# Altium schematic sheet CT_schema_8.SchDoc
size 370 x 245 mm
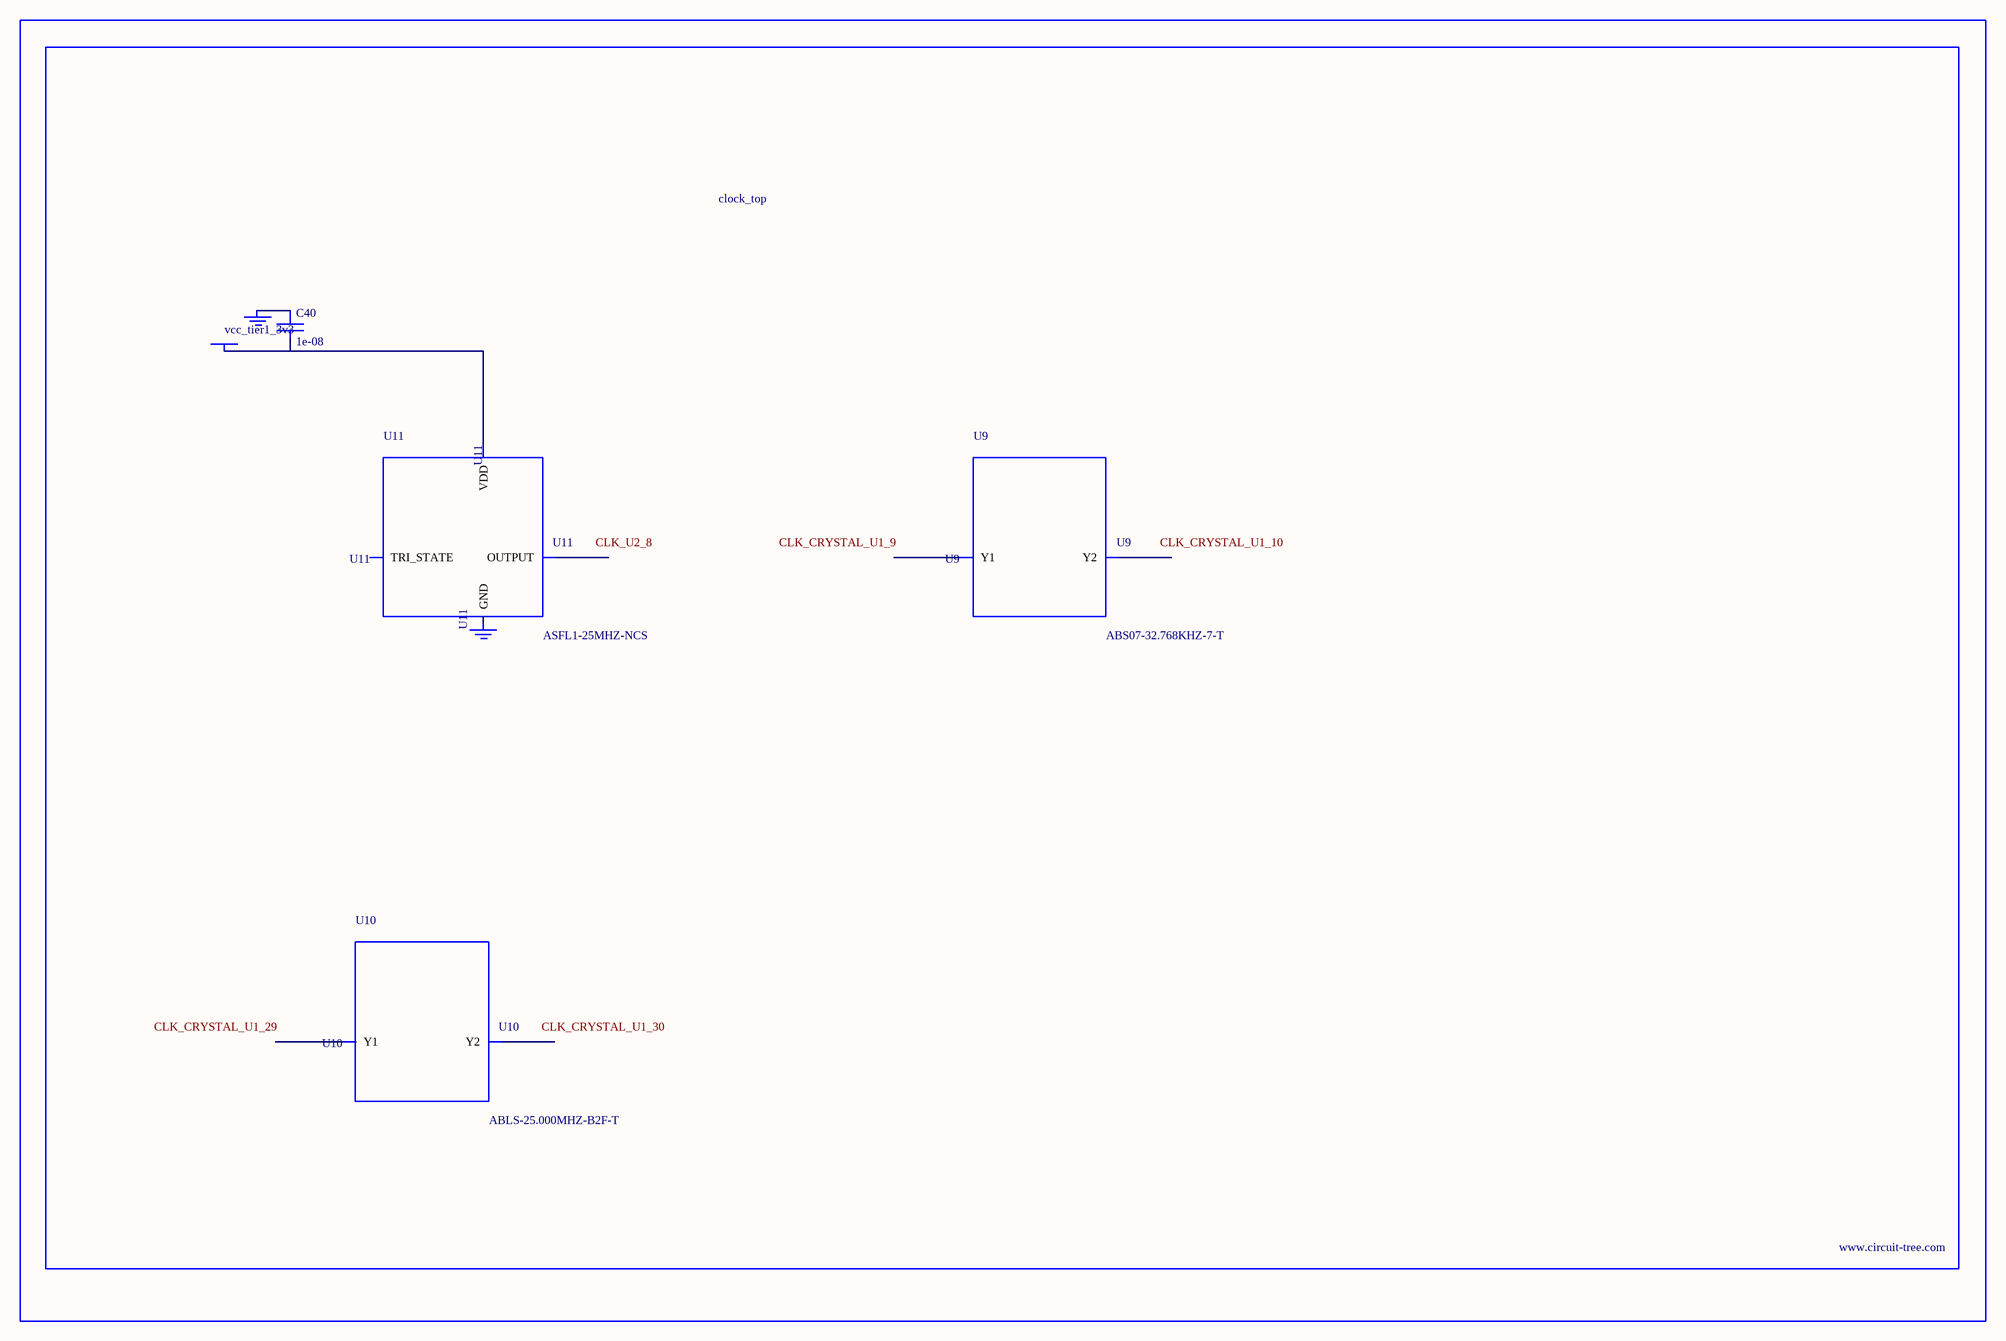
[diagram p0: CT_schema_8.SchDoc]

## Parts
BORDER7  (no value)
C40  1e-08  [C0402]
GND_INSTANCE_7_0  (no value)
GND_INSTANCE_7_1  (no value)
POWER_INSTANCE_7_0  vcc_tier1_3v3
U9  ABS07-32.768KHZ-7-T  [ABS07-32.768KHZ-7-T]
U10  ABLS-25.000MHZ-B2F-T  [ABLS-25.000MHZ-B2F-T]
U11  ASFL1-25MHZ-NCS  [ASFL1]

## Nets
NetC40_1: C40.1 GND_INSTANCE_7_0.0(GND)
NetC40_2: C40.2 POWER_INSTANCE_7_0.0(PWR) U11.4(VDD)

Not connected (* = marked no-connect by the designer): GND_INSTANCE_7_1 0(GND); U9 1(Y1) 2(Y2); U10 1(Y1) 2(Y2); U11 1(TRI_STATE) 2(GND) 3(OUTPUT)

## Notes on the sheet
- Labels drawn without touching a wire or pin: CLK_CRYSTAL_U1_9, CLK_CRYSTAL_U1_10, CLK_CRYSTAL_U1_29, CLK_CRYSTAL_U1_30, CLK_U2_8

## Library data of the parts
BORDER7 = BORDER_PAGE7
C40 = C0402C103K3RAC
GND_INSTANCE_7_0 GND_INSTANCE_7_1 = GND
POWER_INSTANCE_7_0 = PWR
